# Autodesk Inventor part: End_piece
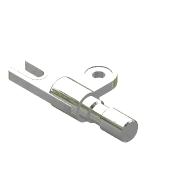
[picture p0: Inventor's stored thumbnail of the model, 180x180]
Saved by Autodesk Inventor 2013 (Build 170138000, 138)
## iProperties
Shininess: 25.0
Length Units: 11269
Angle Units: 11279
Time Units: 11290
Mass Units: 11283
Length Display Precision: 3
Angle Display Precision: 2
Created: 2001-04
Part Number: End_piece
Material: Standard
Document SubType Name: Modellieren
Designer: dl
Density: 1 g/cm^3
Density: 0.0
Volumn: 0.0
Area: 0.0
PropertySet Name: Model Information
Control State: 0
Master: False
Checked Out: False
Author: dl
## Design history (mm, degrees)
sketch "Sketch1"
  geometry: L1 (0.768, 2.744)-(-15.607, 2.744); L2 (-17.316, 9.566)-(16.876, 25.46); L3 (47.768, 29.994)-(47.768, 10.994); L4 (47.768, 10.994)-(49.268, 10.994); L5 (49.268, 10.994)-(49.268, -15.006); L6 (49.268, -15.006)-(-15.607, -15.006); L7 (0.768, -7.756)-(-15.607, -7.756); C1 r 5 at (33.768, 29.994); A1 r 5.25 centre (0.768, -2.506) between (0.768, -7.756) and (0.768, 2.744); A2 r 3.625 centre (-15.607, 6.369) between (-17.316, 9.566) and (-15.607, 2.744); A3 r 3.625 centre (-15.607, -11.381) between (-15.607, -7.756) and (-15.607, -15.006); A4 r 14 centre (33.768, 29.994) between (47.768, 29.994) and (19.768, 29.994); A5 r 5 centre (14.768, 29.994) between (16.876, 25.46) and (19.768, 29.994)
  constraints: 14 end point, 10 point on circle, 8 tangent, 6 centre point, 4 parallel, 1 coincident, 1 horizontal, 1 perpendicular
  dimensions: "d0" = 14 radius of A4; "d1" = 10.5 distance of L7.end L1.end; "d2" = 3.625 radius of A2; "d3" = 12.5 distance from line of L6 A1.centre; "d5" = 16.375 horizontal distance of A3.centre A1.centre (computed from d2); "d6" = 0 horizontal distance of A3.centre A2.centre; "d7" = 32.5 vertical distance of A1.centre A4.centre; "d8" = 48.5 distance from line of L5 A1.centre; "d9" = 15.5 distance from line of A4.centre L5; "d10" = 26 distance of L4.end L5.end; "d11" = 1.5 distance of L3.end L4.end (derived); "d12" = 5 radius of A5; "d13" = 180 deg dimension on A4.centre L3.start A4.end; "d15" = 26.77237 distance from line of L4.end L2; "d16" = 10 diameter of C1
extrude "Extrusion1" new body sketch "Sketch1" stored distance "d17" = 8; taper "d18" = 0 deg
sketch "Sketch3"
  geometry: L1 (0.768, 2.744)-(-15.607, 2.744) reference; L2 (-15.607, -7.756)-(0.768, -7.756) reference; L3 (-19.178, 5.744)-(0.768, 5.744); L4 (0.768, -10.756)-(-19.178, -10.756); L5 (54.768, -15.006)-(49.268, -15.006) reference; L6 (49.268, -15.006)-(-15.607, -15.006) reference; L7 (-19.178, -10.756)-(-25.029, -10.756) reference; L8 (-25.029, -10.756)-(-25.029, 5.744) reference; L9 (-25.029, 5.744)-(-19.178, 5.744) reference; L10 (-17.316, 9.566)-(16.876, 25.46) reference; L11 (47.768, 29.994)-(47.768, 12.494) reference; L12 (49.268, 10.994)-(49.268, 9.994) reference; L13 (49.268, 9.994)-(54.768, 9.994) reference; L14 (54.768, 9.994)-(54.768, 6.919) reference; L15 (54.768, 6.919)-(63.087, 6.919) reference; L16 (63.087, 6.919)-(64.768, 5.238) reference; L17 (64.768, 5.238)-(74.768, 5.238) reference; L18 (74.768, 5.238)-(76.45, 6.919) reference; L19 (76.45, 6.919)-(98.768, 6.919) reference; L20 (98.768, 6.919)-(99.768, 5.919) reference; L21 (99.768, 5.919)-(99.768, -10.931) reference; L22 (99.768, -10.931)-(98.768, -11.931) reference; L23 (98.768, -11.931)-(76.45, -11.931) reference; L24 (76.45, -11.931)-(74.768, -10.249) reference; L25 (74.768, -10.249)-(64.768, -10.249) reference; L26 (64.768, -10.249)-(63.087, -11.931) reference; L27 (63.087, -11.931)-(54.768, -11.931) reference; L28 (54.768, -11.931)-(54.768, -15.006) reference; C1 r 5 at (33.768, 29.994) reference; A1 r 5.25 centre (0.768, -2.506) between (0.768, -7.756) and (0.768, 2.744) reference; A2 r 8.25 centre (0.768, -2.506) between (0.768, -10.756) and (0.768, 5.744); A3 r 3.625 centre (-15.607, 6.369) between (-17.316, 9.566) and (-15.607, 2.744) reference; A4 r 3.625 centre (-15.607, -11.381) between (-15.607, -7.756) and (-15.607, -15.006) reference; A5 r 3.625 centre (-15.607, -11.381) between (-19.178, -10.756) and (-15.607, -15.006) reference; A6 r 3.625 centre (-15.607, 6.369) between (-17.316, 9.566) and (-19.178, 5.744) reference; A7 r 5 centre (14.768, 29.994) between (16.876, 25.46) and (19.768, 29.994) reference; A8 r 14 centre (33.768, 29.994) between (47.768, 29.994) and (19.768, 29.994) reference; A9 r 1.5 centre (49.268, 12.494) between (47.768, 12.494) and (49.268, 10.994) reference
  constraints: 4 end point, 4 point on circle, 1 centre point
  dimensions: "d36" = 3 radial gap between concentric circles of A1 A2
extrude "Extrusion2" join sketch "Sketch3" stored distance "d37" = 8.5; taper "d38" = 0 deg
sketch "Sketch5"
  geometry: C1 r 10.5 at (-33.768, 29.994) reference
extrude "Extrusion3" cut sketch "Sketch5" distance "d50" = 1.05; taper "d51" = 0 deg
body "Solid1"
revolve "Revolution1" stored, may be unused: angle "d28" = 90 deg
chamfer "Chamfer1" distance "d31" = 1; stored, may be unused: second distance "d32" = 1, angle "d57" = 45 deg
fillet "Fillet1" dims "d33" = 3
fillet "Fillet2" dims "d35" = 1.5
fillet "Fillet3" dims "d39" = 0.25
fillet "Fillet4" dims "d40" = 0.5
fillet "Fillet5" dims "d41" = 0.5
sketch "Sketch4"
  geometry: C1 r 5 at (33.768, 29.994) reference; 1 further point
  dimensions: "d42" = 0 distance of C1.centre point (33.768, 29.994)
hole "Hole1" sketch "Sketch4" diameter "d43" = 21; stored, may be unused: countersink angle "d47" = 60 deg, drill point angle "d49" = 0 deg; dims "d44" = 6, "d45" = 4, "d46" = 2, "d48" = 1.05
workaxis "Work Axis1"
workplane "Work Plane1"
workaxis "Work Axis2"
workplane "Work Plane2"
workplane "Work Plane3"
sketch "Sketch2"
  geometry: L1 (23.768, -2.506)-(23.768, 9.994); L2 (23.768, 9.994)-(54.768, 9.994); L3 (54.768, 9.994)-(54.768, 6.919); L4 (54.768, 6.919)-(63.087, 6.919); L5 (63.087, 6.919)-(64.768, 5.238); L6 (64.768, 5.238)-(74.768, 5.238); L7 (74.768, 5.238)-(76.45, 6.919); L8 (76.45, 6.919)-(99.768, 6.919); L9 (99.768, 6.919)-(99.768, -2.506); L10 (23.768, -2.506)-(99.768, -2.506); L11 (49.268, 10.994)-(49.268, -15.006) reference; A1 r 5.25 centre (0.768, -2.506) between (0.768, -7.756) and (0.768, 2.744) reference
  constraints: 20 end point, 4 parallel, 2 perpendicular, 1 collinear, 1 vertical
  dimensions: "d19" = 12.5 distance of L1.start L1.end; "d20" = 31 distance of L1.end L2.end; "d21" = 10 distance of L5.end L6.end; "d22" = 10 horizontal distance of L2.end L5.end; "d23" = 45 deg angle of L5 L6; "d24" = 135 deg angle of L6 L7; "d25" = 76 distance of L1.start L9.end; "d26" = 5.5 distance from line of L11 L3.end; "d27" = 0 distance from line of A1.centre L10; "d29" = 9.425 distance of L8.end L9.end; "d30" = 7.74367 distance between parallel lines of L10 L6
other parameters: "d14" = 26.77237, "d52" = 0, "d53" = 0, "d54" = 90 deg, "d55" = 90 deg, "d56" = -52.5
